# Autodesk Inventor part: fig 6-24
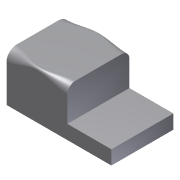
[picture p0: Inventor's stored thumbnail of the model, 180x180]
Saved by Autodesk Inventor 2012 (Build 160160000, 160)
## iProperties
Created: 2004-05
Part Number: fig 6-24
Document SubType Name: Modeling
Designer: CADCIM Technologies
Manufacturer: Standard
Standards Organization: Custom
Density: 1 g/cm^3
Material: Default
Author: CADCIM Technologies
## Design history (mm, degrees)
node "Sketch1"
sketch "Sketch2"
  geometry: L1 (0.098, 47.711)-(0.098, 0.049); L2 (0.098, 0.049)-(-105.483, 0.049); L3 (-105.483, 0.049)-(-105.483, 14.192); L4 (-105.483, 14.192)-(-61.139, 14.192); L5 (-61.139, 14.192)-(-61.139, 47.711); L6 (-61.139, 47.711)-(0.098, 47.711)
  constraints: 12 end point, 3 parallel, 2 perpendicular, 1 vertical
extrude "Extrusion1" new body sketch "Sketch2" stored distance "d0" = 62.5; taper "d1" = 0 deg
fillet "Fillet9" dims "d61" = 10, "d62" = 8, "d63" = 2, "d64" = 5
fillet "Fillet10" dims "d65" = 8, "d66" = 10, "d67" = 2, "d68" = 5
body "Solid1"
